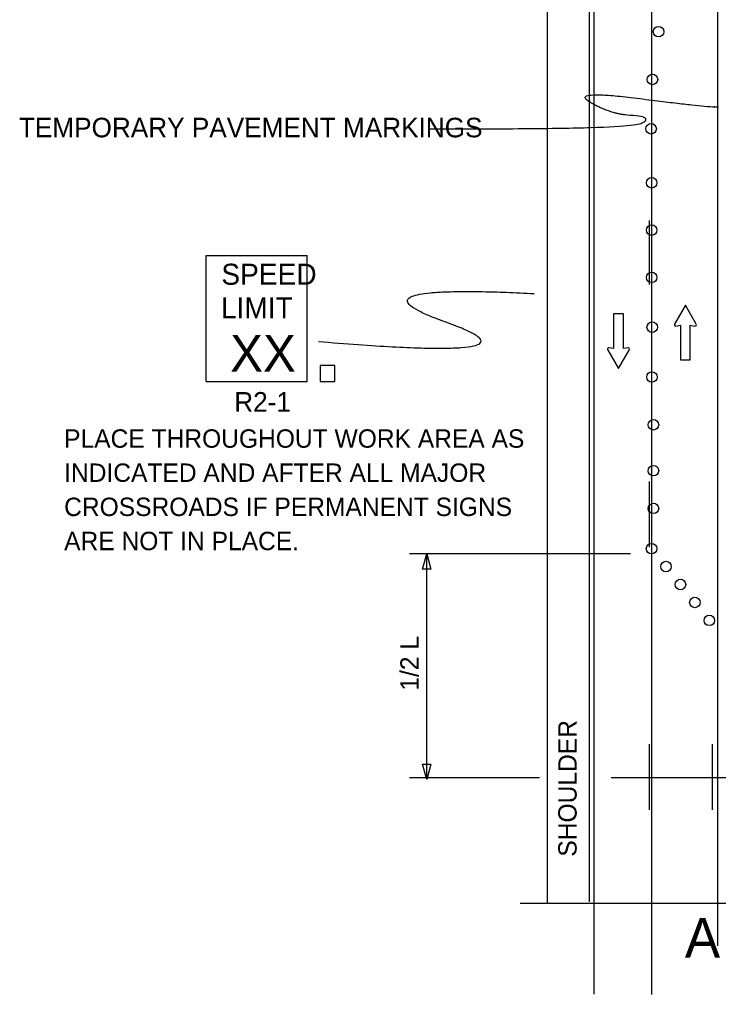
# Model space of a CAD drawing. Extents: x 16038 to 19504, y 5920 to 8321.
# Drawn here: x 16769.4 to 17035.6, y 7333 to 7704.1 of the extents above; entities that cross this region are included whole.
import ezdxf

# ---------------------------------------------------------------- set-up
doc = ezdxf.new("R2010")
doc.units = 0
for name, color, linetype in [('ALI_LEGAL_EX', 7, 'Continuous'), ('MT_SCRATCH_LEVEL_E', 7, 'Continuous'), ('PAVT_EDGE_EX', 7, 'Continuous'), ('TRAFFIC_SIGNS_PR', 7, 'Continuous'), ('TYPICAL_TEXT_DIMEN_PR', 7, 'Continuous')]:
    doc.layers.add(name, color=color, linetype=linetype)

msp = doc.modelspace()

# ---------------------------------------------------------------- linework, layer by layer
at = {"layer": 'ALI_LEGAL_EX'}
for points in [[(17009.25, 7603.26), (17009.25, 7627.57)], [(17009.25, 7503.26), (17009.25, 7528.26)], [(17009.25, 7403.26), (17009.25, 7428.26)], [(17033.25, 7403.26), (17033.25, 7428.26)]]:
    msp.add_lwpolyline(points, dxfattribs=at)
at = {"layer": 'MT_SCRATCH_LEVEL_E'}
for p, q in [((17022.94, 7595.39), (17018.83, 7588.15)), ((17022.94, 7595.39), (17018.83, 7588.15)), ((17027.09, 7588.15), (17022.94, 7595.39)), ((17027.09, 7588.15), (17022.94, 7595.39)), ((16999.35, 7592.11), (16995.61, 7592.11)), ((16995.61, 7592.11), (16995.61, 7578.86)), ((16999.35, 7592.11), (16995.61, 7592.11)), ((16995.61, 7592.11), (16995.61, 7578.86)), ((16999.35, 7578.86), (16999.35, 7592.11)), ((16999.35, 7578.86), (16999.35, 7592.11)), ((17019.31, 7587.46), (17021.09, 7587.78)), ((17019.31, 7587.46), (17021.09, 7587.78)), ((17021.09, 7587.78), (17021.09, 7574.52)), ((17021.09, 7587.78), (17021.09, 7574.52)), ((17024.83, 7574.52), (17024.83, 7587.78)), ((17024.83, 7587.78), (17026.61, 7587.46)), ((17024.83, 7574.52), (17024.83, 7587.78)), ((17024.83, 7587.78), (17026.61, 7587.46)), ((16993.35, 7578.49), (16997.5, 7571.25)), ((16993.35, 7578.49), (16997.5, 7571.25)), ((16995.61, 7578.86), (16993.83, 7579.17)), ((16995.61, 7578.86), (16993.83, 7579.17)), ((16997.5, 7571.25), (17001.61, 7578.49)), ((16997.5, 7571.25), (17001.61, 7578.49)), ((17001.13, 7579.17), (16999.35, 7578.86)), ((17001.13, 7579.17), (16999.35, 7578.86)), ((17021.09, 7574.52), (17024.83, 7574.52)), ((17021.09, 7574.52), (17024.83, 7574.52))]:
    msp.add_line(p, q, dxfattribs=at)
for centre, start, end in [((17019.24, 7587.92), 150.4248, 279.9638), ((17019.24, 7587.92), 150.4248, 279.9638), ((17026.68, 7587.93), 260.0362, 29.7731), ((17026.68, 7587.93), 260.0362, 29.7731), ((16993.76, 7578.71), 80.0362, 209.7731), ((16993.76, 7578.71), 80.0362, 209.7731), ((17001.2, 7578.71), 330.4248, 99.9638), ((17001.2, 7578.71), 330.4248, 99.9638)]:
    msp.add_arc(centre, 0.463, start, end, dxfattribs=at)
at = {"layer": 'PAVT_EDGE_EX'}
for p, q in [((16970.3, 8210.68), (16970.3, 7367.79)), ((16986.3, 8210.68), (16986.3, 7368.22)), ((17035.15, 8180.7), (17035.15, 7351.51)), ((16988.15, 8162.34), (16988.15, 7333.15)), ((17010.01, 8162.15), (17010.01, 7332.97))]:
    msp.add_line(p, q, dxfattribs=at)
at = {"layer": 'TRAFFIC_SIGNS_PR'}
for p, q in [((16840.47, 7614.3), (16878.87, 7614.3)), ((16840.47, 7566.3), (16840.47, 7614.3)), ((16878.87, 7566.3), (16878.87, 7614.3)), ((16840.47, 7566.3), (16878.87, 7566.3))]:
    msp.add_line(p, q, dxfattribs=at)
msp.add_lwpolyline([(16883.89, 7566.3), (16889.48, 7566.3), (16889.48, 7572.47), (16883.89, 7572.47)], close=True, dxfattribs=at)
for centre in [(17012.72, 7699.51), (17010.43, 7681.32), (17009.9, 7662.54), (17010.1, 7641.97), (17010.1, 7623.97), (17010.1, 7605.97), (17010.33, 7587.02), (17010.22, 7568.04), (17010.8, 7549.85), (17010.8, 7532.37), (17010.8, 7518.02), (17010.08, 7502.71), (17015.57, 7495.88), (17021.07, 7489.05), (17026.57, 7482.22), (17032.07, 7475.39)]:
    msp.add_circle(centre, 2, dxfattribs=at)
msp.add_open_spline([(16883.18, 7581.58), (16973.69, 7573.97), (16890.29, 7603.63), (16965.32, 7599.83)], degree=2, dxfattribs=at)
at = {"layer": 'TYPICAL_TEXT_DIMEN_PR'}
for p, q in [((16855.57, 7666.42), (16855.56, 7666.71)), ((17002.04, 7500.74), (16917.94, 7500.74)), ((16922.86, 7494.88), (16924.43, 7500.74)), ((16924.43, 7415.26), (16924.43, 7500.74)), ((16924.43, 7500.74), (16926, 7494.88)), ((16924.43, 7494.88), (16922.86, 7494.88)), ((16926, 7494.88), (16924.43, 7494.88)), ((16924.43, 7414.85), (16922.86, 7420.71)), ((16922.86, 7420.71), (16924.43, 7420.71)), ((16924.43, 7420.71), (16926, 7420.71)), ((16926, 7420.71), (16924.43, 7414.85)), ((16967.37, 7415.4), (16917.94, 7415.39)), ((17071.39, 7415.43), (16994.67, 7415.41)), ((16960.07, 7367.78), (17124.22, 7367.78))]:
    msp.add_line(p, q, dxfattribs=at)
msp.add_open_spline([(16925.07, 7662.57), (17002.08, 7662.27), (17010.78, 7667.11), (16994.28, 7668.02), (16978.88, 7677.42), (17030.64, 7670.84), (17035.57, 7670.84)], degree=2, dxfattribs=at)

# ---------------------------------------------------------------- texts
at = {"layer": 'TRAFFIC_SIGNS_PR'}
for s, height, p in [('TEMPORARY PAVEMENT MARKINGS', 7.449, (16769.14, 7659.29)), ('SPEED', 8, (16846.24, 7603.16)), ('LIMIT', 8, (16846.08, 7590.36)), ('XX', 14.031, (16849.58, 7570.06)), ('R2-1', 7.44, (16851.15, 7554.86)), ('PLACE THROUGHOUT WORK AREA AS', 7, (16786.36, 7541.12)), ('INDICATED AND AFTER ALL MAJOR', 7, (16786.36, 7528.12)), ('CROSSROADS IF PERMANENT SIGNS', 7, (16786.36, 7515.12)), ('ARE NOT IN PLACE.', 7, (16786.36, 7502.12))]:
    msp.add_text(s, height=height, dxfattribs=at).set_placement(p)
at = {"layer": 'TYPICAL_TEXT_DIMEN_PR'}
for s, p in [('1/2 L', (16921.4, 7448.63)), ('SHOULDER', (16981.54, 7385.44))]:
    msp.add_text(s, height=7, rotation=90, dxfattribs=at).set_placement(p)
msp.add_text('A MATCH A', height=15, dxfattribs=at).set_placement((17022.78, 7347.05))

doc.saveas('drawing.dxf')
